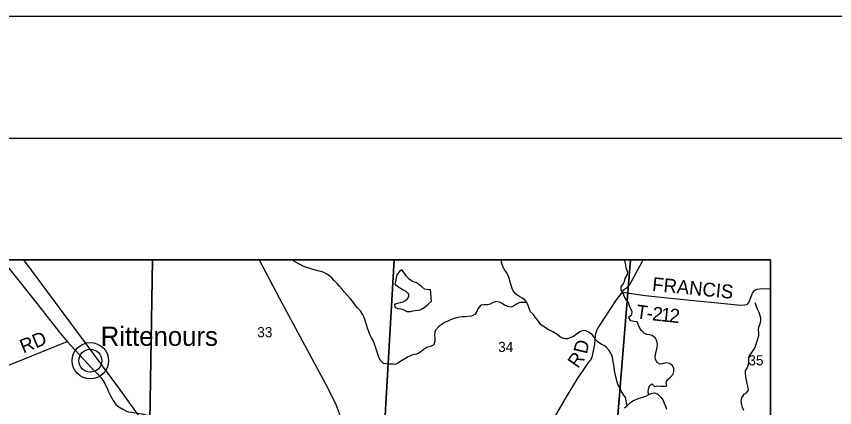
# Model space of a CAD drawing. Extents: x 5.6 to 39.6, y 0.7 to 22.7.
# Drawn here: x 11.957 to 15.315, y 21.1 to 22.707 of the extents above; entities that cross this region are included whole.
import ezdxf

# ---------------------------------------------------------------- set-up
doc = ezdxf.new("R2010")
doc.units = 0
for name, color, linetype in [('Default', 7, 'Continuous'), ('SH_Border', 7, 'Continuous'), ('SH_Cut_Line', 7, 'Continuous'), ('SH_Data', 7, 'Continuous')]:
    doc.layers.add(name, color=color, linetype=linetype)

msp = doc.modelspace()

# ---------------------------------------------------------------- linework, layer by layer
at = {"layer": 'Default'}
for p, q in [((12.515, 21.7074), (11.5581, 21.7074)), ((13.5074, 21.7074), (12.515, 21.7074)), ((14.4767, 21.7074), (13.5074, 21.7074)), ((13.66, 21.5371), (13.656, 21.5849))]:
    msp.add_line(p, q, dxfattribs=at)
for points in [[(15.0518, 18.0251), (15.0518, 21.7074), (8.2518, 21.7074), (8.2518, 18.5322)], [(15.0518, 18.0251), (15.0518, 21.7074), (8.2518, 21.7074), (8.2518, 18.5322)], [(15.0518, 18.0251), (15.0518, 21.7074), (10.4881, 21.7074)], [(11.5581, 21.7074), (11.5015, 21.0544), (12.5031, 20.9635), (12.515, 21.7074)], [(11.8986, 21.7074), (11.9256, 21.6734), (12.0471, 21.5202), (12.1309, 21.4131), (12.1647, 21.3719), (12.2634, 21.2654), (12.2669, 21.2619)], [(12.8355, 20.6493), (12.7687, 20.7217), (12.5342, 20.972), (12.4855, 21.0313), (12.3768, 21.181), (11.9873, 21.7074)], [(12.515, 21.7074), (12.5031, 20.9635), (13.4593, 20.8788), (13.5074, 21.7074)], [(12.9533, 21.7074), (12.9536, 21.7067), (13.0368, 21.5488), (13.2247, 21.1977), (13.2665, 21.1167), (13.2971, 21.0355)], [(14.0523, 21.5321), (14.0228, 21.5314), (14.0091, 21.5251), (13.9973, 21.5169), (13.9867, 21.5133), (13.9735, 21.5154), (13.9603, 21.5209), (13.9502, 21.5278), (13.9397, 21.534), (13.9261, 21.5357), (13.9132, 21.5317), (13.9014, 21.5251), (13.8908, 21.5218), (13.876, 21.5224), (13.8628, 21.5207), (13.8512, 21.5057), (13.8466, 21.4947), (13.8381, 21.4827), (13.8252, 21.4761), (13.8112, 21.4744), (13.7998, 21.4738), (13.7873, 21.4732), (13.7767, 21.4718), (13.7623, 21.4686), (13.7494, 21.4646), (13.7384, 21.4609), (13.7274, 21.4558), (13.7167, 21.4506), (13.7038, 21.4425), (13.69, 21.4328), (13.6774, 21.4182), (13.6742, 21.4083), (13.673, 21.3977), (13.6739, 21.3863), (13.6742, 21.3731), (13.6706, 21.3587), (13.6569, 21.3517), (13.644, 21.3481), (13.631, 21.3414), (13.618, 21.331), (13.6085, 21.3239), (13.5986, 21.3202), (13.5891, 21.3185), (13.5793, 21.3156), (13.5648, 21.3082), (13.5504, 21.3008), (13.5351, 21.2911), (13.5256, 21.284), (13.5115, 21.2778), (13.4983, 21.2783), (13.4854, 21.2793), (13.4748, 21.2798), (13.4627, 21.2815), (13.4493, 21.2949), (13.4435, 21.3117), (13.4391, 21.3235), (13.4347, 21.3368), (13.4303, 21.3494), (13.4263, 21.3612), (13.4205, 21.3757), (13.4145, 21.3864), (13.4061, 21.4029), (13.4028, 21.4124), (13.3995, 21.423), (13.3951, 21.4356), (13.3911, 21.4486), (13.3878, 21.4585), (13.3838, 21.471), (13.3772, 21.484), (13.3694, 21.4978), (13.356, 21.5101), (13.3482, 21.5201), (13.3366, 21.5369), (13.3284, 21.5465), (13.3135, 21.5634), (13.302, 21.5757), (13.2934, 21.5868), (13.2833, 21.5987), (13.2729, 21.6094), (13.261, 21.6229), (13.252, 21.6329), (13.2419, 21.6413), (13.231, 21.6491), (13.2186, 21.6557), (13.2073, 21.6592), (13.1937, 21.6621), (13.1738, 21.6676), (13.1583, 21.6728), (13.1451, 21.6771), (13.1338, 21.6818), (13.121, 21.6877), (13.1079, 21.6943), (13.0977, 21.7009), (13.0895, 21.7074)], [(13.5074, 21.7074), (13.4593, 20.8788), (14.4061, 20.8339), (14.4767, 21.7074)], [(14.4628, 21.1081), (14.456, 21.1423), (14.4467, 21.1557), (14.4386, 21.1698), (14.4327, 21.1835), (14.4268, 21.1931), (14.4224, 21.2053), (14.4191, 21.2175), (14.417, 21.2273), (14.4137, 21.2407), (14.4112, 21.2532), (14.4095, 21.2653), (14.4081, 21.2752), (14.4063, 21.2885), (14.4042, 21.2995), (14.4013, 21.3113), (14.3966, 21.3243), (14.3895, 21.3346), (14.3791, 21.3476), (14.3686, 21.3554), (14.3576, 21.3593), (14.3441, 21.3686), (14.3337, 21.3797), (14.3285, 21.3892), (14.3196, 21.4004), (14.3049, 21.41), (14.294, 21.4155), (14.2816, 21.4172), (14.2694, 21.4109), (14.2553, 21.4024), (14.2435, 21.393), (14.2328, 21.3879), (14.2191, 21.3831), (14.2097, 21.3825), (14.1987, 21.386), (14.1863, 21.393), (14.1755, 21.4004), (14.1578, 21.4112), (14.1473, 21.4167), (14.1372, 21.4218), (14.1263, 21.4287), (14.112, 21.4392), (14.1031, 21.4488), (14.0938, 21.4618), (14.0864, 21.4721), (14.0785, 21.4828), (14.067, 21.494), (14.0614, 21.507), (14.0574, 21.5199), (14.0523, 21.5321), (14.0437, 21.5432), (14.0329, 21.5494), (14.0223, 21.5553), (14.0062, 21.5665), (13.9958, 21.5799), (13.991, 21.5898), (13.987, 21.6031), (13.9838, 21.6161), (13.9809, 21.6275), (13.9765, 21.6408), (13.9676, 21.6546), (13.9617, 21.6645), (13.9565, 21.6745), (13.9506, 21.6878), (13.9481, 21.6973), (13.9476, 21.7074)], [(14.1654, 21.0594), (14.213, 21.1425), (14.2609, 21.221), (14.2825, 21.2521), (14.3025, 21.2809), (14.3108, 21.2919), (14.3142, 21.2972), (14.3168, 21.304), (14.3206, 21.3135), (14.3304, 21.3609), (14.3334, 21.3969), (14.3356, 21.4094), (14.3405, 21.4208), (14.3522, 21.4401), (14.4191, 21.5425), (14.4436, 21.5751), (14.4474, 21.5827), (14.453, 21.5869), (14.4651, 21.5952), (14.4742, 21.6058), (14.5168, 21.6847), (14.5289, 21.7074)], [(14.4767, 21.7074), (14.4061, 20.8339), (14.469, 20.831), (15.0518, 20.8015)], [(14.5527, 21.1539), (14.549, 21.1619), (14.5503, 21.1759), (14.5546, 21.1892), (14.5645, 21.1974), (14.5757, 21.1866), (14.5894, 21.1895), (14.6015, 21.1886), (14.6163, 21.188), (14.6257, 21.1898), (14.624, 21.2023), (14.6272, 21.2144), (14.6409, 21.2252), (14.6524, 21.2379), (14.6552, 21.2489), (14.6554, 21.2606), (14.6498, 21.2728), (14.6371, 21.281), (14.6227, 21.2838), (14.6087, 21.2806), (14.5988, 21.2784), (14.5864, 21.285), (14.5794, 21.2973), (14.578, 21.3083), (14.5808, 21.3238), (14.5844, 21.3366), (14.5864, 21.348), (14.5873, 21.3605), (14.5848, 21.3738), (14.58, 21.3852), (14.5665, 21.396), (14.5567, 21.3991), (14.5447, 21.4012), (14.5334, 21.4059), (14.5221, 21.417), (14.5155, 21.427), (14.5081, 21.4422), (14.504, 21.4533), (14.4916, 21.4534), (14.4787, 21.457), (14.4695, 21.4715), (14.4828, 21.4827), (14.4837, 21.4949), (14.4752, 21.5098), (14.4716, 21.5219), (14.4687, 21.5322), (14.4601, 21.5418), (14.4508, 21.5582), (14.4487, 21.5681), (14.439, 21.5845), (14.4385, 21.5982), (14.4465, 21.6079), (14.4531, 21.6181), (14.4555, 21.6306), (14.4644, 21.6468), (14.466, 21.6573), (14.4594, 21.6737), (14.4584, 21.6863), (14.4548, 21.6996), (14.4517, 21.7074)], [(15.0518, 20.8015), (15.0518, 21.7074), (14.4767, 21.7074)], [(13.656, 21.5849), (13.6462, 21.5843), (13.6322, 21.5872), (13.6188, 21.5976), (13.609, 21.6064), (13.5993, 21.6123), (13.5895, 21.6154), (13.5782, 21.6209), (13.5685, 21.6282), (13.5569, 21.6409), (13.5476, 21.6539), (13.5383, 21.6662), (13.5284, 21.6595), (13.5188, 21.6479), (13.516, 21.6346), (13.514, 21.6218), (13.5096, 21.6089), (13.5205, 21.5985), (13.5332, 21.5908), (13.5445, 21.5842), (13.555, 21.5784), (13.5658, 21.5683), (13.5657, 21.5558), (13.5568, 21.5415), (13.5435, 21.533), (13.5325, 21.5301), (13.5188, 21.5276), (13.5086, 21.524), (13.5099, 21.5134), (13.5223, 21.5079), (13.5352, 21.5062), (13.5472, 21.5022), (13.5592, 21.4956), (13.574, 21.4954), (13.5842, 21.4976), (13.5937, 21.4986), (13.6047, 21.4999), (13.6145, 21.5025), (13.6256, 21.5084), (13.6351, 21.5151), (13.6473, 21.5248), (13.66, 21.5371)], [(14.4436, 21.5751), (14.5379, 21.561), (14.6553, 21.5486), (14.93, 21.5216), (14.9467, 21.5221), (14.9554, 21.5238), (14.9589, 21.5264), (14.9635, 21.5351), (14.9771, 21.5708), (14.9859, 21.5809), (14.9974, 21.5868), (15.0168, 21.5895), (15.0518, 21.5882)], [(14.9421, 21.0887), (14.9373, 21.1009), (14.9341, 21.1123), (14.9316, 21.1271), (14.9336, 21.1408), (14.944, 21.155), (14.9536, 21.1606), (14.9613, 21.1726), (14.9588, 21.1878), (14.9563, 21.1996), (14.9527, 21.2129), (14.9502, 21.2285), (14.9489, 21.2418), (14.9497, 21.2516), (14.9567, 21.2652), (14.9614, 21.2773), (14.9623, 21.289), (14.9625, 21.3019), (14.9645, 21.3121), (14.9718, 21.3226), (14.981, 21.335), (14.9872, 21.3448), (14.9919, 21.3569), (14.9955, 21.369), (14.9994, 21.3833), (15.0034, 21.3965), (15.0035, 21.4087), (15.0025, 21.4204), (15.0038, 21.431), (15.0096, 21.4438), (15.0124, 21.4567), (15.0114, 21.4677), (15.0093, 21.4776), (15.0049, 21.4909), (15.0001, 21.5023), (14.9942, 21.5161), (14.9883, 21.5305)], [(11.2533, 21.1688), (11.3341, 21.244), (11.3451, 21.2538), (11.3504, 21.2584), (11.3579, 21.2622), (11.3708, 21.2634), (11.7716, 21.2273), (11.7826, 21.2258), (11.7936, 21.2254), (11.8057, 21.2281), (11.8235, 21.233), (12.1647, 21.3719)], [(12.2669, 21.2619), (12.2868, 21.242), (12.3027, 21.2245), (12.3107, 21.2143), (12.3193, 21.1989), (12.3302, 21.1756), (12.3353, 21.1648)], [(12.3353, 21.1648), (12.343, 21.1484), (12.3538, 21.1289), (12.3653, 21.1133), (12.3778, 21.103), (12.3931, 21.0934), (12.4056, 21.0877), (12.4149, 21.0835), (12.4302, 21.081), (12.4723, 21.0746), (12.4934, 21.0697), (12.5058, 21.0639), (12.5163, 21.0587), (12.5253, 21.0515), (12.535, 21.0441), (12.5471, 21.0276), (12.5559, 21.0117), (12.5641, 20.993), (12.574, 20.9753), (12.581, 20.9613), (12.5883, 20.9498), (12.5998, 20.9367), (12.6121, 20.9237), (12.6265, 20.9105)], [(14.4529, 21.0999), (14.4628, 21.1081), (14.477, 21.1219), (14.4869, 21.1282), (14.5082, 21.1378), (14.5184, 21.1407), (14.5283, 21.1436), (14.5397, 21.1469), (14.5527, 21.1539), (14.5625, 21.1583), (14.5754, 21.1612), (14.5883, 21.1573), (14.6025, 21.1415), (14.6091, 21.132), (14.615, 21.1183), (14.6206, 21.1061), (14.6246, 21.0942)]]:
    msp.add_lwpolyline(points, dxfattribs=at)
for radius in [0.0744, 0.0472]:
    msp.add_circle((12.2601, 21.293), radius, dxfattribs=at)
at = {"layer": 'SH_Border'}
msp.add_lwpolyline([(7.5518, 22.2074), (39.0518, 22.2074), (39.0518, 1.2074), (7.5518, 1.2074)], close=True, dxfattribs=at)
at = {"layer": 'SH_Cut_Line'}
msp.add_lwpolyline([(5.5518, 0.7074), (39.5518, 0.7074), (39.5518, 22.7074), (5.5518, 22.7074)], close=True, dxfattribs=at)
at = {"layer": 'SH_Data'}
for p, q in [((8.0518, 21.7074), (15.0518, 21.7074)), ((15.0518, 21.7074), (15.0518, 14.7074))]:
    msp.add_line(p, q, dxfattribs=at)

# ---------------------------------------------------------------- texts
at = {"layer": 'Default'}
for s, height, rotation, p in [('FRANCIS', 0.05682, 354.3375, (14.5643, 21.5798)), ('T', 0.0568, 352.1148, (14.4973, 21.4677)), ('2', 0.0568, 353.9475, (14.5646, 21.459)), ('1', 0.0568, 354.0911, (14.5995, 21.4553)), ('2', 0.0568, 354.1204, (14.6344, 21.4517)), ('-', 0.0568, 353.6348, (14.541, 21.4616)), ('Rittenours', 0.07891, 0, (12.3027, 21.354)), ('33', 0.04182, 0, (12.9452, 21.3895)), ('RD', 0.05682, 22.3531, (11.9853, 21.3224)), ('34', 0.04182, 0, (13.934, 21.3286)), ('D', 0.0568, 76.8812, (14.2975, 21.3178)), ('R', 0.0568, 54.686, (14.2609, 21.2583)), ('35', 0.04182, 0, (14.9607, 21.2736))]:
    msp.add_text(s, height=height, rotation=rotation, dxfattribs=at).set_placement(p)

doc.saveas('drawing.dxf')
